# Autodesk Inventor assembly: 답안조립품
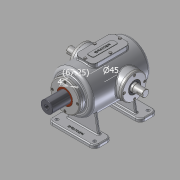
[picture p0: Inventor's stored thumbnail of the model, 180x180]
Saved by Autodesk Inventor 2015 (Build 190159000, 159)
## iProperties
Created: 2016-02
Part Number: 답안조립품
Document SubType Name: Assembly
Designer: Administrator
Mass: 8191.33 g
Surface Area: 4241.86 cm^2
Volume: 1855.51 cm^3
Density: 4.41461 g/cm^3
Author: Administrator
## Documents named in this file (15)
- C:\Users\Administrator\Desktop\360220V1003\답안조립품.iam
- C:\Users\Administrator\Desktop\360220V1003\본체.ipt
- C:\Users\Administrator\Desktop\360220V1003\베어링 6205.ipt
- 베어링 6205.ipt
- C:\Users\Administrator\Desktop\360220V1003\축 커버.ipt
- C:\Users\Administrator\Desktop\360220V1003\오일실.ipt
- 오일실.ipt
- C:\Users\Administrator\Desktop\360220V1003\볼트 M4x0.7.ipt
- C:\Users\Administrator\Desktop\360220V1003\편심축.ipt
- C:\Users\Administrator\Desktop\360220V1003\상부커버.ipt
- C:\Users\Administrator\Desktop\360220V1003\육각머리볼트 M4.ipt
- C:\Users\Administrator\Desktop\360220V1003\슬라이드 커버.ipt
- C:\Users\Administrator\Desktop\360220V1003\부시.ipt
- C:\Users\Administrator\Desktop\360220V1003\가변스프링.ipt
- C:\Users\Administrator\Desktop\360220V1003\슬라이드.ipt
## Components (13 placed, 2 different names)
1. 가변스프링:1
2. M4x0.7:1
3. M4x0.7:3
4. M4x0.7:4
5. M4x0.7:5
6. M4x0.7:2
7. M4x0.7:6
8. M4x0.7:7
9. M4x0.7:8
10. M4x0.7:9
11. M4x0.7:10
12. M4x0.7:11
13. M4x0.7:12
